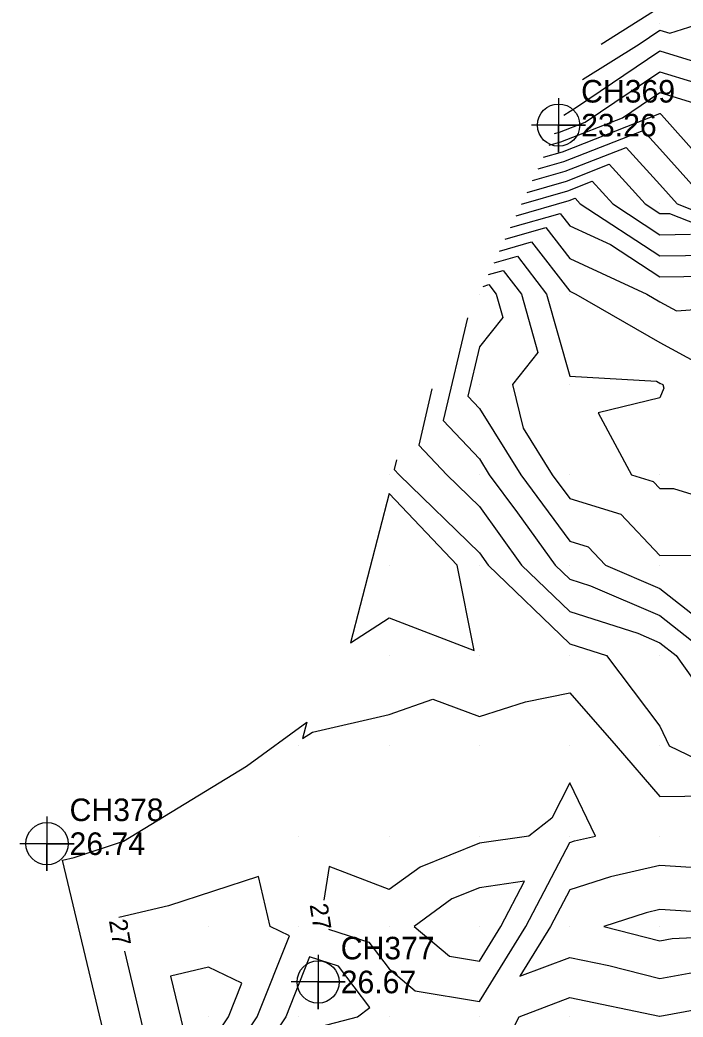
# Model space of a CAD drawing. Extents: x 2531902 to 2533249, y 715219 to 716099.
# Drawn here: x 2532639.1 to 2532712.6, y 715420 to 715530.4 of the extents above; entities that cross this region are included whole.
import ezdxf

# ---------------------------------------------------------------- set-up
doc = ezdxf.new("R2010")
doc.units = 0
for name, color, linetype in [('DTM Contours Major', 7, 'Continuous'), ('DTM Contours Major Text', 7, 'Continuous'), ('DTM Contours Minor', 7, 'Continuous'), ('Exist DTM QL2 LIDAR Elevation Point', 7, 'Continuous'), ('Exist DTM Regular Point CELL', 7, 'Continuous'), ('Exist DTM Regular Point Cogo Elevation', 7, 'Continuous'), ('Exist DTM Regular Point Cogo Number', 7, 'Continuous')]:
    doc.layers.add(name, color=color, linetype=linetype)

msp = doc.modelspace()

# ---------------------------------------------------------------- linework, layer by layer
at = {"layer": 'DTM Contours Major'}
for points in [[(2532701.43, 715523.76), (2532707.7, 715527.68), (2532710, 715529.23), (2532711.1, 715528.9), (2532714.59, 715530), (2532719.13, 715530.87)], [(2532696.5, 715513.88), (2532699.34, 715514.69), (2532708.13, 715518.13), (2532710, 715516.07), (2532715.44, 715510), (2532720, 715508.2), (2532725.82, 715502.7), (2532727.01, 715501.65), (2532729.23, 715502.49), (2532729.85, 715509.68), (2532729.7, 715510), (2532729.83, 715510.17), (2532730, 715510.26), (2532732.15, 715510), (2532740, 715509.6), (2532741.15, 715510), (2532750, 715515.03), (2532756.41, 715513.59), (2532760, 715513.26), (2532767.55, 715512.45), (2532770, 715512.37), (2532776.39, 715513.61), (2532779.91, 715514.7)], [(2532693.45, 715507.37), (2532698.94, 715508.94), (2532700, 715507.57), (2532704.51, 715505.49), (2532710, 715501.9), (2532717.97, 715502.03), (2532720, 715501.23), (2532720.87, 715500.4), (2532729.2, 715493.11), (2532735.49, 715495.49), (2532738.49, 715490), (2532740, 715488.78), (2532747.19, 715480), (2532750, 715474.57), (2532751.14, 715471.14), (2532752.45, 715470), (2532755.99, 715465.99), (2532755.6, 715462.97), (2532754.57, 715456.19), (2532753.22, 715450.72)], [(2532690.4, 715500.86), (2532691.05, 715501.05), (2532691.85, 715500), (2532692.58, 715497.42), (2532690, 715494.18), (2532688.71, 715488.71), (2532690, 715487.34), (2532694.58, 715480), (2532700, 715472.65), (2532702.03, 715472.03), (2532703.96, 715470), (2532710, 715467.42), (2532719.43, 715460)], [(2532700.53, 715439.47), (2532702.85, 715440), (2532700, 715445.88), (2532698.02, 715441.98), (2532695.46, 715440), (2532690, 715439.2), (2532683.43, 715436.57), (2532680, 715434.08), (2532673.37, 715436.63), (2532672.76, 715432.92)], [(2532673.27, 715429.68), (2532677.75, 715428.24), (2532680, 715425.29), (2532682.88, 715422.88), (2532690, 715421.68), (2532695.13, 715430), (2532700, 715439.29), (2532700.53, 715439.47)], [(2532665.39, 715420), (2532668.96, 715428.96), (2532666.82, 715430), (2532665.53, 715435.53), (2532655.58, 715432.27), (2532650.05, 715430.97)], [(2532650.69, 715427.26), (2532653.88, 715413.88), (2532660, 715411.94), (2532665.39, 715420)], [(2532685.87, 715408.15), (2532687.74, 715410), (2532690, 715411.49), (2532694.42, 715420), (2532700, 715422.12), (2532709.93, 715420.07), (2532710, 715420.05), (2532718.39, 715421.61), (2532720, 715421.69), (2532722.31, 715420), (2532720.87, 715419.13), (2532720, 715416.02), (2532713.58, 715410), (2532719.68, 715400.32), (2532719.94, 715400), (2532720, 715399.89), (2532721.98, 715390.85), (2532721.73, 715388.83), (2532722.49, 715382.53), (2532719.24, 715375.74), (2532714.71, 715373.54)]]:
    msp.add_lwpolyline(points, dxfattribs=at)
at = {"layer": 'DTM Contours Minor'}
for points in [[(2532699.36, 715519.83), (2532700.75, 715520.7), (2532710, 715526.93), (2532714.43, 715525.57), (2532720, 715527.34), (2532721.96, 715528.04), (2532728.82, 715530), (2532729.82, 715530.18), (2532730, 715530.2), (2532731.24, 715530), (2532740, 715528.49), (2532741.67, 715528.33), (2532750, 715528.23), (2532751.86, 715528.14), (2532760, 715527.54), (2532762.5, 715527.5), (2532770, 715527.89), (2532771.83, 715528.17), (2532773.77, 715530), (2532780, 715535.55)], [(2532697.72, 715516.48), (2532699.03, 715516.85), (2532705.85, 715519.52), (2532710, 715522.32), (2532717.57, 715520), (2532720, 715516.87), (2532721.37, 715518.63), (2532723.91, 715520), (2532728.38, 715521.62), (2532730, 715522.08), (2532736.09, 715523.91), (2532740, 715523.24), (2532747.46, 715522.54), (2532750, 715522.51), (2532757.89, 715522.11), (2532760, 715521.95), (2532768.18, 715521.82), (2532770, 715521.92), (2532777.03, 715522.97), (2532780, 715525.78), (2532782.98, 715527.02), (2532783.98, 715530), (2532783.66, 715533.66)], [(2532703.5, 715527.68), (2532710, 715531.76)], [(2532698.33, 715517.78), (2532698.88, 715517.94), (2532701.72, 715519.05), (2532710, 715524.62), (2532717.75, 715522.25), (2532720, 715522.96), (2532725.17, 715524.83), (2532730, 715526.21), (2532732.91, 715527.09), (2532740, 715525.86), (2532744.57, 715525.43), (2532750, 715525.37), (2532754.88, 715525.12), (2532760, 715524.75), (2532765.34, 715524.66), (2532770, 715524.91), (2532774.43, 715525.57), (2532779.12, 715530), (2532780, 715530.79)], [(2532697.11, 715515.18), (2532699.19, 715515.77), (2532709.98, 715520), (2532710, 715520.01), (2532710.04, 715520), (2532710.16, 715519.84), (2532718.97, 715510)], [(2532695.89, 715512.58), (2532699.49, 715513.61), (2532706.25, 715516.25), (2532710, 715512.13), (2532711.91, 715510), (2532720, 715506.8)], [(2532695.28, 715511.27), (2532699.64, 715512.52), (2532704.38, 715514.38), (2532708.35, 715510), (2532710, 715508.92), (2532711.06, 715508.94), (2532720, 715505.41)], [(2532694.67, 715509.97), (2532699.8, 715511.44), (2532702.5, 715512.5), (2532704.77, 715510), (2532710, 715506.58), (2532713.37, 715506.63)], [(2532694.06, 715508.67), (2532699.95, 715510.36), (2532700.62, 715510.62), (2532701.18, 715510), (2532710, 715504.24), (2532715.67, 715504.33)], [(2532692.84, 715506.07), (2532697.36, 715507.36), (2532700, 715503.94), (2532708.54, 715500), (2532710, 715499.16), (2532711.84, 715498.16), (2532720, 715498.73)], [(2532692.23, 715504.77), (2532695.78, 715505.78), (2532700, 715500.32), (2532700.69, 715500), (2532710, 715494.66), (2532718.56, 715490)], [(2532691.62, 715503.47), (2532694.21, 715504.21), (2532697.45, 715500), (2532700, 715490.93), (2532709.62, 715490.38), (2532710, 715490.16), (2532710.3, 715490), (2532710.42, 715489.58), (2532710, 715488.51), (2532703.15, 715486.85), (2532706.84, 715480), (2532709.26, 715479.26), (2532710, 715478.48), (2532711.5, 715478.5), (2532720, 715475.87)], [(2532691.01, 715502.16), (2532692.63, 715502.63), (2532694.65, 715500), (2532696.47, 715493.53), (2532693.66, 715490), (2532694.84, 715485.16), (2532698.06, 715480), (2532700, 715477.37), (2532705.65, 715475.65), (2532710, 715471.05), (2532718.88, 715471.12)], [(2532688.68, 715497.36), (2532686, 715486), (2532690, 715481.77), (2532691.1, 715480), (2532694.21, 715475.79), (2532698.38, 715470), (2532700, 715468.44), (2532702.29, 715467.71), (2532710, 715464.42), (2532715.61, 715460)], [(2532684.75, 715489.5), (2532683.28, 715483.28), (2532686.39, 715480), (2532690, 715476.49), (2532694.68, 715470), (2532700, 715464.87), (2532707.54, 715462.46), (2532710, 715461.41), (2532711.79, 715460), (2532716.23, 715453.77), (2532718.01, 715450), (2532720, 715449.04), (2532726.96, 715440), (2532730, 715433.6), (2532732.62, 715430), (2532734.43, 715424.43), (2532733.53, 715415.87)], [(2532680.82, 715481.65), (2532680.57, 715480.57), (2532681.11, 715480), (2532690, 715471.35), (2532690.97, 715470), (2532700, 715461.3), (2532704.06, 715460), (2532710, 715452.18), (2532711.03, 715450), (2532720, 715445.67), (2532724.37, 715440), (2532728.32, 715431.68), (2532720, 715431.3), (2532718.68, 715431.32), (2532710, 715431.86), (2532708.49, 715431.51), (2532703.77, 715430), (2532710, 715428.41), (2532711.34, 715428.66), (2532720, 715429.07), (2532723.46, 715426.54), (2532730, 715425.84), (2532731.43, 715421.43), (2532731.14, 715418.67)], [(2532689.44, 715460.56), (2532687.55, 715470), (2532680, 715477.94), (2532675.71, 715461.41), (2532680, 715464.15), (2532689.44, 715460.56)], [(2532650.29, 715410.29), (2532643.83, 715437.32), (2532645.12, 715437.62), (2532650.59, 715439.42), (2532664.2, 715447.74), (2532670.87, 715452.62), (2532670.4, 715450.8), (2532671.5, 715451.5), (2532680, 715453.45), (2532684.84, 715455.16), (2532690, 715453.24), (2532695.12, 715454.88), (2532700, 715455.87), (2532705.15, 715450), (2532710, 715444.38), (2532715.54, 715444.46)], [(2532713.46, 715436.54), (2532710, 715436.75), (2532704.51, 715435.49), (2532700, 715434.04), (2532697.88, 715430), (2532694.48, 715424.48), (2532700, 715426.57), (2532704.32, 715425.68), (2532710, 715424.23), (2532714.87, 715425.13)], [(2532692.38, 715430), (2532695, 715435), (2532690, 715434.27), (2532686.95, 715433.05), (2532682.76, 715430), (2532686.7, 715426.7), (2532690, 715426.14), (2532692.38, 715430)], [(2532677.88, 715421.04), (2532674.39, 715425.61), (2532671.17, 715426.64), (2532670, 715423.64), (2532668.55, 715420), (2532665.63, 715415.63), (2532670, 715418.3), (2532676.51, 715420), (2532677.88, 715421.04)], [(2532662.22, 715420), (2532663.7, 715423.7), (2532660, 715425.49), (2532655.8, 715424.5), (2532657.47, 715417.47), (2532660, 715416.67), (2532662.22, 715420)]]:
    msp.add_lwpolyline(points, dxfattribs=at)
at = {"layer": 'Exist DTM QL2 LIDAR Elevation Point'}
for p, q in [((2532710, 715530), (2532710, 715530)), ((2532710, 715520), (2532710, 715520)), ((2532700, 715510), (2532700, 715510)), ((2532710, 715510), (2532710, 715510)), ((2532690, 715500), (2532690, 715500)), ((2532700, 715500), (2532700, 715500)), ((2532710, 715500), (2532710, 715500)), ((2532690, 715490), (2532690, 715490)), ((2532700, 715490), (2532700, 715490)), ((2532710, 715490), (2532710, 715490)), ((2532680, 715480), (2532680, 715480)), ((2532690, 715480), (2532690, 715480)), ((2532700, 715480), (2532700, 715480)), ((2532710, 715480), (2532710, 715480)), ((2532680, 715470), (2532680, 715470)), ((2532690, 715470), (2532690, 715470)), ((2532700, 715470), (2532700, 715470)), ((2532710, 715470), (2532710, 715470)), ((2532680, 715460), (2532680, 715460)), ((2532690, 715460), (2532690, 715460)), ((2532700, 715460), (2532700, 715460)), ((2532710, 715460), (2532710, 715460)), ((2532670, 715450), (2532670, 715450)), ((2532680, 715450), (2532680, 715450)), ((2532690, 715450), (2532690, 715450)), ((2532700, 715450), (2532700, 715450)), ((2532710, 715450), (2532710, 715450)), ((2532670, 715440), (2532670, 715440)), ((2532680, 715440), (2532680, 715440)), ((2532690, 715440), (2532690, 715440)), ((2532700, 715440), (2532700, 715440)), ((2532710, 715440), (2532710, 715440)), ((2532660, 715430), (2532660, 715430)), ((2532670, 715430), (2532670, 715430)), ((2532680, 715430), (2532680, 715430)), ((2532690, 715430), (2532690, 715430)), ((2532700, 715430), (2532700, 715430)), ((2532710, 715430), (2532710, 715430)), ((2532660, 715420), (2532660, 715420)), ((2532670, 715420), (2532670, 715420)), ((2532680, 715420), (2532680, 715420)), ((2532690, 715420), (2532690, 715420)), ((2532700, 715420), (2532700, 715420)), ((2532710, 715420), (2532710, 715420))]:
    msp.add_line(p, q, dxfattribs=at)
at = {"layer": 'Exist DTM Regular Point CELL'}
for points in [[(2532698.77, 715521.71), (2532698.77, 715515.71), (2532698.77, 715518.71), (2532701.77, 715518.71), (2532695.77, 715518.71)], [(2532642.11, 715442.16), (2532642.11, 715436.16), (2532642.11, 715439.16), (2532645.11, 715439.16), (2532639.11, 715439.16)], [(2532672.14, 715426.85), (2532672.14, 715420.85), (2532672.14, 715423.85), (2532675.14, 715423.85), (2532669.14, 715423.85)]]:
    msp.add_lwpolyline(points, dxfattribs=at)
for centre in [(2532698.77, 715518.71), (2532642.11, 715439.16), (2532672.14, 715423.85)]:
    msp.add_circle(centre, 2.34, dxfattribs=at)

# ---------------------------------------------------------------- texts
at = {"layer": 'DTM Contours Major Text'}
for rotation, p in [(278.9657, (2532671.19, 715432.4)), (279.7384, (2532648.96, 715430.64))]:
    msp.add_text('27', height=2, rotation=rotation, dxfattribs=at).set_placement(p)
at = {"layer": 'Exist DTM Regular Point Cogo Elevation'}
for s, p in [('23.26', (2532701.27, 715517.46)), ('26.74', (2532644.61, 715437.91)), ('26.67', (2532674.64, 715422.6))]:
    msp.add_text(s, height=2.5, dxfattribs=at).set_placement(p)
at = {"layer": 'Exist DTM Regular Point Cogo Number'}
for s, p in [('CH369', (2532701.27, 715521.21)), ('CH378', (2532644.61, 715441.66)), ('CH377', (2532674.64, 715426.35))]:
    msp.add_text(s, height=2.5, dxfattribs=at).set_placement(p)

doc.saveas('drawing.dxf')
